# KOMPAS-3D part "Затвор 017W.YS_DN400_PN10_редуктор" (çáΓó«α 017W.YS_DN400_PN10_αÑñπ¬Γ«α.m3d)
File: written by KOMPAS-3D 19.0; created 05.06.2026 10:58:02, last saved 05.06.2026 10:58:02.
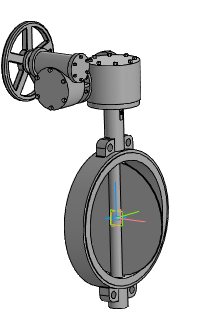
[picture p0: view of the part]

Document properties: Автор: Энергия; Полное имя файла: ..\..\..\3d для проектировщиков\x.x Тип 017W.Y(S) Затвор дисковый поворотный межфланцевый\Затвор 017W.Y(S)_DN50-DN1200_редуктор\Затвор 017W.YS_DN400_PN10_редуктор.a3d

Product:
- Part/product: Затвор 017W.YS_DN400_PN10_редуктор
    Масса: 117.828

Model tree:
1. Операция без истории:1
